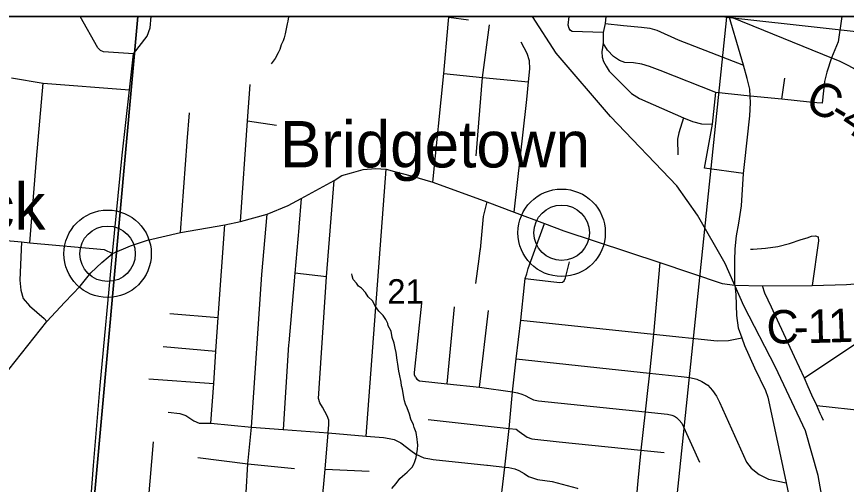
# Model space of a CAD drawing. Extents: x 0 to 34, y -2 to 22.
# Drawn here: x 3.329 to 4.743, y 20.104 to 20.9 of the extents above; entities that cross this region are included whole.
import ezdxf

# ---------------------------------------------------------------- set-up
doc = ezdxf.new("R2010")
doc.units = 0
for name, color, linetype in [('Default', 7, 'Continuous'), ('GM_X_County_Road', 7, 'Continuous'), ('GM_X_County_Road_Text', 7, 'Continuous'), ('GM_X_Minor_River', 7, 'Continuous'), ('GM_X_Rail_Line', 7, 'Continuous'), ('GM_X_Section', 7, 'Continuous'), ('GM_X_Section_Text', 7, 'Continuous'), ('GM_X_State_Route', 7, 'Continuous'), ('GM_X_Township_Road', 7, 'Continuous'), ('GM_X_Unincorporated', 7, 'Continuous'), ('GM_X_Unincorporated_Location', 7, 'Continuous'), ('GM_X_Unincorporated_Text', 7, 'Continuous'), ('SH_Cut_Line', 7, 'Continuous'), ('SH_Data', 7, 'Continuous')]:
    doc.layers.add(name, color=color, linetype=linetype)

msp = doc.modelspace()

# ---------------------------------------------------------------- linework, layer by layer
at = {"layer": 'Default'}
for points in [[(3.5359, 20.9), (2.5176, 20.9), (2.4387, 20.1012), (3.4541, 19.9967)], [(4.5319, 20.9), (3.5359, 20.9), (3.4541, 19.9967), (4.4338, 19.8873), (4.539, 20.8993)], [(4.5391, 20.9), (4.5319, 20.9), (4.539, 20.8993)], [(5.5559, 20.9), (4.5391, 20.9), (4.539, 20.8993), (5.5442, 20.7879)]]:
    msp.add_lwpolyline(points, close=True, dxfattribs=at)
at = {"layer": 'GM_X_County_Road'}
for points in [[(3.5282, 20.8367), (3.4772, 20.8401), (3.4719, 20.8422), (3.4676, 20.8469), (3.4372, 20.9)], [(3.5282, 20.8367), (3.5514, 20.8665), (3.5568, 20.8808), (3.5586, 20.9)], [(4.5527, 20.4429), (4.5527, 20.4668), (4.5527, 20.4849), (4.5534, 20.5046), (4.5553, 20.5267), (4.5594, 20.5486), (4.5639, 20.5781), (4.5676, 20.633), (4.5693, 20.6481), (4.578, 20.7313), (4.5792, 20.7534), (4.5789, 20.7648), (4.578, 20.7763), (4.5736, 20.7945), (4.5673, 20.8173), (4.5619, 20.8364), (4.543, 20.9)], [(4.544, 20.9), (4.6014, 20.877), (4.7171, 20.83), (4.7302, 20.8245), (4.7429, 20.8183), (4.755, 20.8124), (4.769, 20.804), (4.7817, 20.7966), (4.7972, 20.7861), (4.8584, 20.743), (4.8656, 20.7381), (4.9228, 20.6977), (4.9297, 20.6929), (4.9549, 20.6749), (5.0196, 20.629)], [(3.4928, 20.4968), (3.509, 20.6643), (3.5214, 20.7752), (3.5282, 20.8367)], [(2.9785, 20.6012), (3.0897, 20.5413), (3.1017, 20.5364), (3.1176, 20.5345), (3.3055, 20.5196), (3.3376, 20.5164)], [(3.3376, 20.5164), (3.3348, 20.4512), (3.3364, 20.4346), (3.3402, 20.42), (3.3513, 20.4076), (3.3762, 20.3862), (3.3809, 20.3811)], [(3.3376, 20.5164), (3.3515, 20.515), (3.4786, 20.5034), (3.4928, 20.4968)], [(3.4093, 19.4828), (3.4238, 19.6478), (3.4244, 19.6548), (3.4345, 19.795), (3.4391, 19.8586), (3.4438, 19.9231), (3.4481, 19.9478), (3.4491, 19.9932), (3.4599, 20.136), (3.4715, 20.2724), (3.4928, 20.4968)], [(4.5527, 20.4429), (4.6, 20.4416), (4.6842, 20.4426), (4.7427, 20.4442), (4.8109, 20.449), (4.828, 20.4497), (4.8765, 20.4525), (4.918, 20.4563), (4.9672, 20.4585)]]:
    msp.add_lwpolyline(points, dxfattribs=at)
at = {"layer": 'GM_X_Minor_River'}
for points in [[(3.7924, 20.9), (3.7924, 20.8999), (3.791, 20.8924), (3.7901, 20.8879), (3.7887, 20.8818), (3.7878, 20.8762), (3.7865, 20.8705), (3.7847, 20.8641), (3.783, 20.8585), (3.7801, 20.8517), (3.7776, 20.8442), (3.7747, 20.8386), (3.7695, 20.8289), (3.7663, 20.8244), (3.7627, 20.8196)], [(3.9843, 20.2776), (3.9817, 20.2913), (3.9804, 20.2967), (3.9785, 20.3085), (3.9776, 20.3154), (3.9758, 20.3284), (3.9741, 20.3357), (3.9725, 20.3441), (3.9691, 20.3541), (3.9672, 20.3644), (3.9622, 20.3737), (3.9616, 20.3779), (3.958, 20.3845), (3.9537, 20.3911), (3.9463, 20.3986), (3.9405, 20.4064), (3.9355, 20.4161), (3.9282, 20.4232), (3.9235, 20.4306), (3.9166, 20.438), (3.9113, 20.4412), (3.9081, 20.4463), (3.9026, 20.4526), (3.9006, 20.4587), (3.9003, 20.4622)], [(3.9685, 20.0968), (3.9757, 20.1053), (3.982, 20.1138), (3.9864, 20.1179), (3.9942, 20.1248), (4.0028, 20.1332), (4.0061, 20.1385), (4.0073, 20.143), (4.0099, 20.1497), (4.0109, 20.1569), (4.0118, 20.1633), (4.0125, 20.1709), (4.0123, 20.1751), (4.0113, 20.1808), (4.0098, 20.1919), (4.0063, 20.2008), (4.0053, 20.205), (4.0007, 20.215), (3.9987, 20.2231), (3.9942, 20.2339), (3.9917, 20.2401), (3.9897, 20.2462), (3.9887, 20.2516), (3.9865, 20.2661), (3.9848, 20.2715), (3.9843, 20.2776)]]:
    msp.add_lwpolyline(points, dxfattribs=at)
at = {"layer": 'GM_X_Rail_Line'}
for points in [[(7.2924, 18.0527), (7.3254, 18.3889), (7.3765, 18.917), (7.3781, 18.9333), (7.4316, 19.4382), (7.4466, 19.581), (7.5261, 20.3339), (7.5512, 20.5718), (7.5526, 20.5853), (7.5548, 20.6102), (7.5809, 20.9), (2.1, 20.9)], [(4.6999, 19.3545), (4.657, 19.4903), (4.6508, 19.5786), (4.6577, 19.6755), (4.679, 19.7614), (4.7115, 19.9173), (4.7104, 20.0292), (4.6947, 20.1189), (4.6732, 20.1949), (4.6217, 20.3034), (4.5682, 20.4079), (4.536, 20.4795), (4.4891, 20.5622), (4.454, 20.6117), (4.3411, 20.73), (4.2485, 20.8379), (4.2078, 20.9)]]:
    msp.add_lwpolyline(points, dxfattribs=at)
at = {"layer": 'GM_X_Section'}
msp.add_lwpolyline([(4.539, 20.8993), (5.5442, 20.7879), (5.4475, 19.8207), (4.8002, 19.892), (4.7992, 19.8486), (4.4338, 19.8873)], close=True, dxfattribs=at)
at = {"layer": 'GM_X_State_Route'}
for points in [[(3.4854, 20.4906), (3.4928, 20.4968), (3.5234, 20.5097), (3.5519, 20.5197), (3.6082, 20.5326), (3.6841, 20.5457), (3.7103, 20.5512), (3.7561, 20.5639), (3.792, 20.5785), (3.8141, 20.5903), (3.8701, 20.621), (3.8834, 20.6296), (3.8994, 20.6341), (3.9193, 20.6399), (3.9407, 20.6413), (3.9588, 20.6404), (3.973, 20.6366), (4.0011, 20.629), (4.0381, 20.6181), (4.1304, 20.5846), (4.1768, 20.5671), (4.2282, 20.5477), (4.2614, 20.5351), (4.4246, 20.4813), (4.5308, 20.4457), (4.5527, 20.4429)], [(3.4116, 20.4137), (3.4376, 20.4412), (3.4558, 20.464), (3.4742, 20.4812), (3.4854, 20.4906)], [(4.5527, 20.4429), (4.5542, 20.4271), (4.5557, 20.3915), (4.5582, 20.3702), (4.5643, 20.353), (4.5689, 20.3403), (4.5862, 20.3024), (4.605, 20.2636), (4.6089, 20.2525), (4.6287, 20.1597), (4.64, 20.1064), (4.6474, 20.0712), (4.6532, 20.0414), (4.6516, 20.0031), (4.6513, 19.9951), (4.6505, 19.9548)], [(2.7521, 20.1556), (2.756, 20.155), (2.8155, 20.1533), (2.8429, 20.1537), (2.9026, 20.1559), (2.9768, 20.1606), (3.05, 20.1771), (3.1038, 20.1937), (3.1276, 20.1996), (3.1742, 20.211), (3.1958, 20.2163), (3.2439, 20.2311), (3.2569, 20.2377), (3.2863, 20.2636), (3.2937, 20.2723), (3.3809, 20.3811), (3.4116, 20.4137)]]:
    msp.add_lwpolyline(points, dxfattribs=at)
at = {"layer": 'GM_X_Township_Road'}
for p, q in [((4.6329, 20.7597), (4.6377, 20.7952)), ((3.6198, 20.6877), (3.6239, 20.7362)), ((3.7227, 20.7228), (3.7719, 20.7155)), ((3.9245, 20.186), (3.9588, 20.6404)), ((4.5676, 20.633), (4.5012, 20.6423)), ((3.8141, 20.5903), (3.8099, 20.5415)), ((3.8573, 20.4568), (3.8032, 20.4636)), ((4.0624, 20.275), (4.0753, 20.4063)), ((4.1178, 20.2692), (4.1331, 20.3995)), ((3.5902, 20.3944), (3.6728, 20.3881)), ((4.8019, 20.3724), (4.6712, 20.2844)), ((3.5789, 20.3383), (3.6687, 20.3303)), ((3.5547, 20.2833), (3.6649, 20.2753)), ((4.6921, 20.2379), (4.7768, 20.229)), ((4.7039, 20.2125), (4.7011, 20.2186)), ((3.855, 20.1298), (3.9295, 20.1262))]:
    msp.add_line(p, q, dxfattribs=at)
for points in [[(4.0645, 20.887), (4.0652, 20.8988), (4.0987, 20.8946)], [(4.3283, 20.8729), (4.2753, 20.8748), (4.2726, 20.8761), (4.2705, 20.8796), (4.2688, 20.8853), (4.2702, 20.9)], [(4.3331, 20.9), (4.3318, 20.8885), (4.3283, 20.8729), (4.3283, 20.8548), (4.3261, 20.8402), (4.3266, 20.831), (4.3288, 20.8236), (4.3333, 20.8157), (4.3386, 20.8073), (4.3765, 20.769), (4.3903, 20.7604), (4.4654, 20.7277), (4.4804, 20.7217), (4.4958, 20.7176), (4.5145, 20.7171)], [(4.7347, 20.9), (4.7288, 20.8572), (4.7171, 20.83), (4.7095, 20.8053), (4.7056, 20.7894), (4.7016, 20.7526), (4.6924, 20.7532), (4.6796, 20.7544), (4.6329, 20.7597), (4.5789, 20.7648), (4.52, 20.7707), (4.4253, 20.8082), (4.4073, 20.8149), (4.3943, 20.819), (4.3799, 20.8212), (4.3655, 20.8217), (4.3561, 20.8251), (4.3458, 20.8323), (4.3359, 20.8426), (4.3283, 20.8548)], [(4.0381, 20.6181), (4.0572, 20.8031), (4.0645, 20.887)], [(4.1121, 20.6632), (4.1229, 20.7962), (4.1346, 20.8862)], [(4.3318, 20.8885), (4.3629, 20.8849), (4.3936, 20.8822), (4.408, 20.8801), (4.42, 20.8767), (4.4563, 20.8604), (4.5673, 20.8173)], [(4.1981, 20.7588), (4.2013, 20.7889), (4.2033, 20.8113), (4.2029, 20.8248), (4.1989, 20.8373), (4.1884, 20.8567)], [(3.3203, 20.7958), (3.3745, 20.7868), (3.5214, 20.7752)], [(4.0572, 20.8031), (4.1229, 20.7962), (4.2013, 20.7889)], [(3.3515, 20.515), (3.3628, 20.6573), (3.3745, 20.7868)], [(3.7103, 20.5512), (3.7227, 20.7228), (3.7271, 20.7842)], [(4.5012, 20.6423), (4.5145, 20.7171), (4.52, 20.7707)], [(4.1768, 20.5671), (4.1976, 20.7538), (4.1981, 20.7588)], [(4.4654, 20.7277), (4.4573, 20.7023), (4.4552, 20.6914), (4.4556, 20.665)], [(3.6082, 20.5326), (3.6197, 20.6867), (3.6198, 20.6877)], [(3.8412, 19.9505), (3.8444, 20.0087), (3.8491, 20.068), (3.855, 20.1298), (3.8598, 20.1915), (3.8609, 20.2055), (3.8611, 20.2134), (3.858, 20.2203), (3.8504, 20.235), (3.8456, 20.2429), (3.8437, 20.2502), (3.8573, 20.4568), (3.8701, 20.621)], [(4.1304, 20.5846), (4.124, 20.56), (4.1186, 20.5034), (4.1184, 20.502)], [(3.7293, 20.2013), (3.7468, 20.461), (3.7561, 20.5639)], [(3.6602, 20.208), (3.6649, 20.2753), (3.6687, 20.3303), (3.6728, 20.3881), (3.6841, 20.5457)], [(3.8099, 20.5415), (3.8098, 20.5405), (3.8032, 20.4636), (3.793, 20.345)], [(4.1512, 20.0513), (4.1607, 20.133), (4.168, 20.199), (4.1739, 20.2615), (4.1803, 20.3176), (4.1882, 20.3836), (4.1944, 20.4435), (4.1956, 20.4545), (4.1982, 20.462), (4.2007, 20.4714), (4.2282, 20.5477)], [(4.5792, 20.5042), (4.5836, 20.5041), (4.6048, 20.5056), (4.6257, 20.5089), (4.6459, 20.5139), (4.6656, 20.5208), (4.6759, 20.5234), (4.6835, 20.5263), (4.6899, 20.527), (4.6946, 20.5251), (4.6949, 20.5184), (4.6842, 20.4426)], [(4.1184, 20.502), (4.1165, 20.4875), (4.1109, 20.4457)], [(4.1956, 20.4545), (4.2445, 20.4483), (4.2547, 20.4473), (4.2589, 20.4478), (4.262, 20.4502), (4.2644, 20.4552), (4.2708, 20.4826)], [(4.4246, 20.4813), (4.4143, 20.3593), (4.4073, 20.2929)], [(4.6182, 20.399), (4.6153, 20.4052), (4.6039, 20.4292), (4.6, 20.4416)], [(4.0084, 20.2862), (4.0068, 20.2901), (4.007, 20.2943), (4.0194, 20.4122)], [(4.6837, 20.2559), (4.6773, 20.2696), (4.6712, 20.2844), (4.6543, 20.3209), (4.6182, 20.399)], [(4.1882, 20.3836), (4.4143, 20.3593), (4.5228, 20.3479), (4.5417, 20.3488), (4.5643, 20.353)], [(3.793, 20.345), (3.7926, 20.3411), (3.7835, 20.1971)], [(4.1803, 20.3176), (4.4073, 20.2929), (4.4612, 20.2875), (4.4759, 20.286), (4.488, 20.2831), (4.4966, 20.2787), (4.5064, 20.2726), (4.5148, 20.2635), (4.5216, 20.2542), (4.5263, 20.2437), (4.5727, 20.1416), (4.5802, 20.1313), (4.5943, 20.1206), (4.61, 20.1127), (4.64, 20.1064)], [(4.0084, 20.2862), (4.0111, 20.283), (4.0155, 20.28), (4.0624, 20.275), (4.1178, 20.2692), (4.1739, 20.2615), (4.1823, 20.2597), (4.1898, 20.2573), (4.1957, 20.2549), (4.2026, 20.251), (4.2095, 20.248), (4.2184, 20.2462), (4.4, 20.2273), (4.4381, 20.2236), (4.4454, 20.2219), (4.4498, 20.2201), (4.4535, 20.2176), (4.458, 20.2133), (4.4622, 20.2079), (4.4923, 20.1419)], [(4.4073, 20.2929), (4.4043, 20.2685), (4.4, 20.2273), (4.3924, 20.1619), (4.3896, 20.1329)], [(4.7011, 20.2186), (4.6982, 20.2246), (4.6921, 20.2379), (4.6837, 20.2559)], [(3.5871, 20.2268), (3.6072, 20.2245), (3.6174, 20.2212), (3.6312, 20.2118), (3.6402, 20.2082), (3.6602, 20.208), (3.7293, 20.2013), (3.7835, 20.1971), (3.8598, 20.1915), (3.9245, 20.186), (3.954, 20.1835), (3.9638, 20.1821), (3.9726, 20.1802), (3.9839, 20.1743), (4.0006, 20.1613), (4.0094, 20.1555), (4.0228, 20.149), (4.0331, 20.1473)], [(4.0304, 20.2142), (4.168, 20.199), (4.1799, 20.1978), (4.1854, 20.1941), (4.1989, 20.184), (4.207, 20.1812), (4.2533, 20.1763)], [(3.7203, 20.0901), (3.723, 20.1386), (3.7293, 20.2013)], [(3.6564, 19.9016), (3.5617, 19.9109), (3.5565, 19.9138), (3.5517, 19.9173), (3.5473, 19.9232), (3.5438, 19.932), (3.5427, 19.9438), (3.5459, 19.9821), (3.5624, 20.1761)], [(4.2533, 20.1763), (4.3924, 20.1619), (4.4323, 20.1579)], [(3.6379, 20.1493), (3.723, 20.1386), (3.8026, 20.1306)], [(4.0331, 20.1473), (4.0387, 20.1463), (4.1301, 20.1364), (4.1311, 20.1363)], [(4.1311, 20.1363), (4.1607, 20.133), (4.1678, 20.1323), (4.1777, 20.1302), (4.1848, 20.1276), (4.1937, 20.1223), (4.2014, 20.1174), (4.2166, 20.1121), (4.2417, 20.109), (4.284, 20.0971), (4.285, 20.097)], [(4.3896, 20.1329), (4.3873, 20.1096), (4.3849, 20.0844), (4.3796, 20.0234), (4.3718, 19.9637), (4.3638, 19.8887)]]:
    msp.add_lwpolyline(points, dxfattribs=at)
at = {"layer": 'GM_X_Unincorporated'}
for centre, radius in [((4.2576, 20.5321), 0.0744), ((3.4842, 20.4963), 0.0744), ((4.2576, 20.5321), 0.0472), ((3.4842, 20.4963), 0.0472)]:
    msp.add_circle(centre, radius, dxfattribs=at)
at = {"layer": 'GM_X_Unincorporated_Location'}
for p, q in [((4.2576, 20.5321), (4.2576, 20.5321)), ((3.4842, 20.4963), (3.4842, 20.4963))]:
    msp.add_line(p, q, dxfattribs=at)
at = {"layer": 'SH_Cut_Line'}
msp.add_lwpolyline([(6.0485, 14.702), (6.1464, 14.7771), (6.2416, 14.8366), (6.3391, 14.8719), (6.8207, 14.994), (7.0052, 15.0295), (7.018, 15.0319), (7.3068, 15.0956), (7.4995, 15.1593), (7.5948, 15.214), (7.6912, 15.289), (7.9856, 15.5639), (8.2003, 15.8586), (8.2596, 15.9572), (8.5337, 16.2495), (8.6286, 16.3042), (8.7283, 16.3459), (8.827, 16.358), (8.9, 16.3574), (8.9, 20.9), (2.1, 20.9)], dxfattribs=at)
at = {"layer": 'SH_Data'}
msp.add_line((2.1, 20.9), (8.9, 20.9), dxfattribs=at)

# ---------------------------------------------------------------- texts
at = {"layer": 'GM_X_County_Road_Text'}
for s, rotation, p in [('C', 334.8407, (4.6693, 20.7439)), ('-', 329.2287, (4.71, 20.7249)), ('4', 325.9216, (4.7291, 20.7135)), ('C', 0.6766, (4.6069, 20.3434)), ('1', 1.2816, (4.677, 20.3443)), ('1', 2.1479, (4.7127, 20.3451)), ('-', 0.8269, (4.6534, 20.344))]:
    msp.add_text(s, height=0.0568, rotation=rotation, dxfattribs=at).set_placement(p)
at = {"layer": 'GM_X_Section_Text'}
msp.add_text('21', height=0.04186, rotation=0, dxfattribs=at).set_placement((3.9606, 20.4112))
at = {"layer": 'GM_X_Unincorporated_Text'}
for s, p in [('Bridgetown', (3.7777, 20.6433)), ('Mack', (3.126, 20.5375))]:
    msp.add_text(s, height=0.07898, rotation=0, dxfattribs=at).set_placement(p)

doc.saveas('drawing.dxf')
